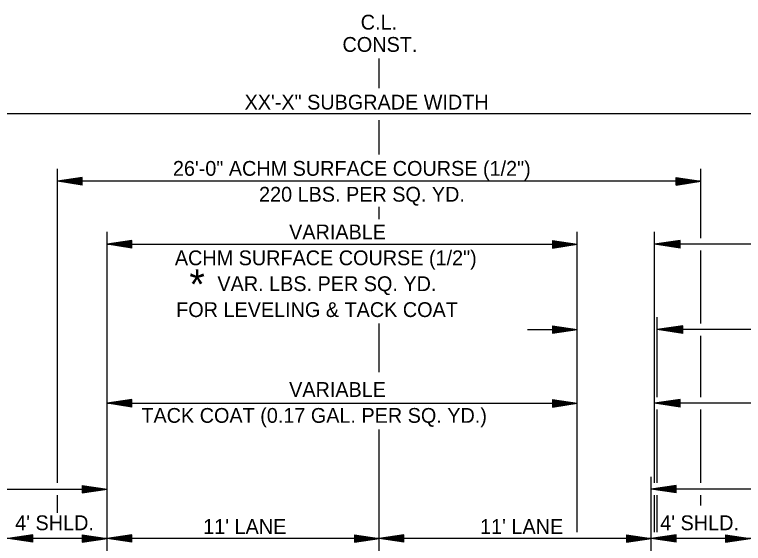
# Model space of a CAD drawing. Extents: x 138 to 3619, y -519 to 1449.
# Drawn here: x 460.6 to 755.2, y -282.8 to -68.8 of the extents above; entities that cross this region are included whole.
import ezdxf

# ---------------------------------------------------------------- set-up
doc = ezdxf.new("R2010")
doc.units = 0
for name, color, linetype in [('R_Annotation', 7, 'Continuous'), ('R_Centerline', 7, 'Continuous'), ('R_Dimension', 7, 'Continuous')]:
    doc.layers.add(name, color=color, linetype=linetype)

msp = doc.modelspace()

# ---------------------------------------------------------------- linework, layer by layer
at = {"layer": 'R_Centerline'}
for p, q in [((608, -98.62), (608, -86.64)), ((608, -125.42), (608, -111.52)), ((608, -151.62), (608, -146.64)), ((608, -213.43), (608, -193.8)), ((608, -272.33), (608, -236.67)), ((608, -320.11), (608, -272.33))]:
    msp.add_line(p, q, dxfattribs=at)
at = {"layer": 'R_Dimension'}
for p, q in [((414.37, -108.81), (801.63, -108.81)), ((477.98, -258.28), (477.98, -131.27)), ((738.02, -159.26), (738.02, -131.27)), ((487.98, -134.77), (477.98, -136.27)), ((487.98, -135.02), (479.65, -136.27)), ((487.98, -135.27), (481.37, -136.27)), ((487.98, -137.77), (487.98, -134.77)), ((728.02, -134.77), (738.02, -136.27)), ((728.02, -137.77), (728.02, -134.77)), ((728.02, -135.02), (736.35, -136.27)), ((728.02, -135.27), (734.63, -136.27)), ((487.98, -137.77), (477.98, -136.27)), ((738.02, -136.27), (477.98, -136.27)), ((487.98, -137.52), (479.65, -136.27)), ((487.98, -137.26), (481.37, -136.27)), ((487.98, -135.52), (483.04, -136.27)), ((487.98, -137.01), (483.04, -136.27)), ((487.98, -135.78), (484.73, -136.27)), ((487.98, -136.75), (484.73, -136.27)), ((487.98, -136.03), (486.4, -136.27)), ((487.98, -136.5), (486.4, -136.27)), ((728.02, -135.52), (732.96, -136.27)), ((728.02, -135.78), (731.27, -136.27)), ((728.02, -136.03), (729.6, -136.27)), ((728.02, -137.77), (738.02, -136.27)), ((728.02, -136.75), (731.27, -136.27)), ((728.02, -137.26), (734.63, -136.27)), ((728.02, -137.52), (736.35, -136.27)), ((728.02, -137.01), (732.96, -136.27)), ((728.02, -136.5), (729.6, -136.27)), ((498, -280.78), (498, -156.76)), ((688, -278.28), (688, -156.76)), ((719.27, -258.28), (719.27, -156.76)), ((508, -160.26), (498, -161.76)), ((508, -163.26), (498, -161.76)), ((498, -161.76), (688, -161.76)), ((508, -160.51), (499.67, -161.76)), ((508, -163.01), (499.67, -161.76)), ((508, -160.76), (501.39, -161.76)), ((508, -162.75), (501.39, -161.76)), ((508, -161.01), (503.06, -161.76)), ((508, -162.5), (503.06, -161.76)), ((508, -161.27), (504.75, -161.76)), ((508, -162.24), (504.75, -161.76)), ((508, -161.52), (506.42, -161.76)), ((508, -161.99), (506.42, -161.76)), ((508, -163.26), (508, -160.26)), ((678.02, -160.26), (688.02, -161.76)), ((678.02, -160.26), (678.02, -163.26)), ((678.02, -160.51), (686.35, -161.76)), ((678.02, -160.76), (684.63, -161.76)), ((678.02, -161.01), (682.96, -161.76)), ((678.02, -161.27), (681.27, -161.76)), ((678.02, -161.52), (679.6, -161.76)), ((678.02, -163.26), (688.02, -161.76)), ((678.02, -162.25), (681.27, -161.76)), ((678.02, -162.75), (684.63, -161.76)), ((678.02, -163.01), (686.35, -161.76)), ((678.02, -162.5), (682.96, -161.76)), ((678.02, -161.99), (679.6, -161.76)), ((729.65, -160.2), (719.27, -161.76)), ((969.27, -161.76), (719.27, -161.76)), ((729.65, -163.32), (719.27, -161.76)), ((729.65, -160.46), (721, -161.76)), ((729.65, -163.06), (721, -161.76)), ((729.65, -160.73), (722.79, -161.76)), ((729.65, -162.79), (722.79, -161.76)), ((729.65, -160.99), (724.51, -161.76)), ((729.65, -162.53), (724.51, -161.76)), ((729.65, -161.25), (726.27, -161.76)), ((729.65, -162.26), (726.27, -161.76)), ((729.65, -161.52), (728.01, -161.76)), ((729.65, -162), (728.01, -161.76)), ((729.65, -163.32), (729.65, -160.2)), ((738.02, -193.77), (738.02, -164.26)), ((720.32, -223.59), (720.32, -191.27)), ((668, -196.27), (688, -196.27)), ((678.02, -194.77), (688.02, -196.27)), ((678.02, -194.77), (678.02, -197.77)), ((678.02, -195.02), (686.35, -196.27)), ((678.02, -195.27), (684.63, -196.27)), ((678.02, -195.52), (682.96, -196.27)), ((678.02, -195.78), (681.27, -196.27)), ((678.02, -196.03), (679.6, -196.27)), ((678.02, -197.77), (688.02, -196.27)), ((678.02, -196.76), (681.27, -196.27)), ((678.02, -197.26), (684.63, -196.27)), ((678.02, -197.52), (686.35, -196.27)), ((678.02, -197.01), (682.96, -196.27)), ((678.02, -196.5), (679.6, -196.27)), ((730.7, -194.71), (720.32, -196.27)), ((970.32, -196.27), (720.32, -196.27)), ((730.7, -197.83), (720.32, -196.27)), ((730.7, -194.97), (722.05, -196.27)), ((730.7, -197.57), (722.05, -196.27)), ((730.7, -195.24), (723.83, -196.27)), ((730.7, -197.3), (723.83, -196.27)), ((730.7, -195.5), (725.56, -196.27)), ((730.7, -197.04), (725.56, -196.27)), ((730.7, -195.76), (727.32, -196.27)), ((730.7, -196.77), (727.32, -196.27)), ((730.7, -196.03), (729.06, -196.27)), ((730.7, -196.51), (729.06, -196.27)), ((730.7, -197.83), (730.7, -194.71)), ((738.02, -223.59), (738.02, -198.77)), ((508, -224.59), (498, -226.09)), ((498, -226.09), (688, -226.09)), ((508, -227.59), (498, -226.09)), ((508, -224.84), (499.67, -226.09)), ((508, -227.34), (499.67, -226.09)), ((508, -225.09), (501.39, -226.09)), ((508, -227.08), (501.39, -226.09)), ((508, -225.34), (503.06, -226.09)), ((508, -226.83), (503.06, -226.09)), ((508, -225.6), (504.75, -226.09)), ((508, -226.57), (504.75, -226.09)), ((508, -225.85), (506.42, -226.09)), ((508, -226.32), (506.42, -226.09)), ((508, -227.59), (508, -224.59)), ((678.02, -224.59), (688.02, -226.09)), ((678.02, -224.59), (678.02, -227.59)), ((678.02, -224.84), (686.35, -226.09)), ((678.02, -225.09), (684.63, -226.09)), ((678.02, -225.34), (682.96, -226.09)), ((678.02, -225.6), (681.27, -226.09)), ((678.02, -225.85), (679.6, -226.09)), ((678.02, -227.59), (688.02, -226.09)), ((678.02, -226.58), (681.27, -226.09)), ((678.02, -227.08), (684.63, -226.09)), ((678.02, -227.34), (686.35, -226.09)), ((678.02, -226.83), (682.96, -226.09)), ((678.02, -226.32), (679.6, -226.09)), ((729.65, -224.53), (719.27, -226.09)), ((969.27, -226.09), (719.27, -226.09)), ((729.65, -227.65), (719.27, -226.09)), ((729.65, -224.79), (721, -226.09)), ((729.65, -227.39), (721, -226.09)), ((729.65, -225.06), (722.79, -226.09)), ((729.65, -227.12), (722.79, -226.09)), ((729.65, -225.32), (724.51, -226.09)), ((729.65, -226.86), (724.51, -226.09)), ((729.65, -225.58), (726.27, -226.09)), ((729.65, -226.59), (726.27, -226.09)), ((729.65, -225.85), (728.01, -226.09)), ((729.65, -226.33), (728.01, -226.09)), ((729.65, -227.65), (729.65, -224.53)), ((720.32, -258.28), (720.32, -228.59)), ((738.02, -258.28), (738.02, -228.59)), ((718, -322.31), (718, -255.78)), ((258, -260.78), (498, -260.78)), ((488, -259.28), (498, -260.78)), ((488, -259.28), (488, -262.28)), ((488, -259.53), (496.33, -260.78)), ((488, -259.79), (494.61, -260.78)), ((488, -260.04), (492.95, -260.78)), ((488, -260.3), (491.25, -260.78)), ((488, -260.55), (489.58, -260.78)), ((488, -262.28), (498, -260.78)), ((488, -261.27), (491.25, -260.78)), ((488, -261.78), (494.61, -260.78)), ((488, -262.03), (496.33, -260.78)), ((488, -261.53), (492.95, -260.78)), ((488, -261.02), (489.58, -260.78)), ((728, -259.28), (718, -260.78)), ((958, -260.78), (718, -260.78)), ((728, -262.28), (718, -260.78)), ((728, -259.53), (719.67, -260.78)), ((728, -262.03), (719.67, -260.78)), ((728, -259.79), (721.39, -260.78)), ((728, -261.78), (721.39, -260.78)), ((728, -260.04), (723.06, -260.78)), ((728, -261.53), (723.06, -260.78)), ((728, -260.29), (724.75, -260.78)), ((728, -261.27), (724.75, -260.78)), ((728, -260.55), (726.42, -260.78)), ((728, -261.02), (726.42, -260.78)), ((728, -262.28), (728, -259.28)), ((477.98, -270.43), (477.98, -263.28)), ((719.27, -278.28), (719.27, -263.28)), ((720.32, -278.28), (720.32, -263.28)), ((738.02, -267.42), (738.02, -263.28)), ((468, -279.28), (458, -280.78)), ((468, -279.53), (459.67, -280.78)), ((468, -279.79), (461.39, -280.78)), ((468, -282.28), (468, -279.28)), ((488, -279.28), (498, -280.78)), ((488, -279.28), (488, -282.28)), ((488, -279.53), (496.33, -280.78)), ((488, -279.79), (494.61, -280.78)), ((508, -279.28), (498, -280.78)), ((508, -279.53), (499.67, -280.78)), ((508, -279.79), (501.39, -280.78)), ((508, -282.28), (508, -279.28)), ((598, -279.28), (608, -280.78)), ((598, -279.28), (598, -282.28)), ((598, -279.53), (606.33, -280.78)), ((598, -279.78), (604.61, -280.78)), ((618, -279.28), (608, -280.78)), ((618, -279.53), (609.67, -280.78)), ((618, -279.79), (611.39, -280.78)), ((618, -282.28), (618, -279.28)), ((708, -279.28), (718, -280.78)), ((708, -279.28), (708, -282.28)), ((708, -279.53), (716.33, -280.78)), ((708, -279.79), (714.61, -280.78)), ((728, -279.28), (718, -280.78)), ((728, -279.53), (719.67, -280.78)), ((728, -279.79), (721.39, -280.78)), ((728, -282.28), (728, -279.28)), ((748, -279.28), (758, -280.78)), ((748, -279.28), (748, -282.28)), ((748, -279.53), (756.33, -280.78)), ((748, -279.79), (754.61, -280.78)), ((801.63, -280.78), (414.37, -280.78)), ((468, -282.28), (458, -280.78)), ((468, -282.03), (459.67, -280.78)), ((468, -281.78), (461.39, -280.78)), ((468, -280.04), (463.06, -280.78)), ((468, -281.53), (463.06, -280.78)), ((468, -280.29), (464.75, -280.78)), ((468, -281.27), (464.75, -280.78)), ((468, -280.55), (466.42, -280.78)), ((468, -281.02), (466.42, -280.78)), ((488, -280.04), (492.95, -280.78)), ((488, -280.3), (491.25, -280.78)), ((488, -280.55), (489.58, -280.78)), ((488, -282.28), (498, -280.78)), ((488, -281.27), (491.25, -280.78)), ((488, -281.78), (494.61, -280.78)), ((488, -282.03), (496.33, -280.78)), ((488, -281.53), (492.95, -280.78)), ((488, -281.02), (489.58, -280.78)), ((498, -317.91), (498, -280.78)), ((508, -282.28), (498, -280.78)), ((508, -282.03), (499.67, -280.78)), ((508, -281.78), (501.39, -280.78)), ((508, -280.04), (503.06, -280.78)), ((508, -281.53), (503.06, -280.78)), ((508, -280.29), (504.75, -280.78)), ((508, -281.27), (504.75, -280.78)), ((508, -280.55), (506.42, -280.78)), ((508, -281.02), (506.42, -280.78)), ((598, -280.03), (602.94, -280.78)), ((598, -280.29), (601.25, -280.78)), ((598, -280.54), (599.58, -280.78)), ((598, -282.28), (608, -280.78)), ((598, -281.27), (601.25, -280.78)), ((598, -281.77), (604.61, -280.78)), ((598, -282.03), (606.33, -280.78)), ((598, -281.52), (602.94, -280.78)), ((598, -281.01), (599.58, -280.78)), ((618, -282.28), (608, -280.78)), ((618, -282.03), (609.67, -280.78)), ((618, -281.78), (611.39, -280.78)), ((618, -280.04), (613.06, -280.78)), ((618, -281.53), (613.06, -280.78)), ((618, -280.29), (614.75, -280.78)), ((618, -281.27), (614.75, -280.78)), ((618, -280.55), (616.42, -280.78)), ((618, -281.02), (616.42, -280.78)), ((708, -280.04), (712.95, -280.78)), ((708, -280.3), (711.25, -280.78)), ((708, -280.55), (709.58, -280.78)), ((708, -282.28), (718, -280.78)), ((708, -281.27), (711.25, -280.78)), ((708, -281.78), (714.61, -280.78)), ((708, -282.03), (716.33, -280.78)), ((708, -281.53), (712.95, -280.78)), ((708, -281.02), (709.58, -280.78)), ((728, -282.28), (718, -280.78)), ((728, -282.03), (719.67, -280.78)), ((728, -281.78), (721.39, -280.78)), ((728, -280.04), (723.06, -280.78)), ((728, -281.53), (723.06, -280.78)), ((728, -280.29), (724.75, -280.78)), ((728, -281.27), (724.75, -280.78)), ((728, -280.55), (726.42, -280.78)), ((728, -281.02), (726.42, -280.78)), ((748, -280.04), (752.95, -280.78)), ((748, -280.3), (751.25, -280.78)), ((748, -280.55), (749.58, -280.78)), ((748, -282.28), (758, -280.78)), ((748, -281.27), (751.25, -280.78)), ((748, -281.78), (754.61, -280.78)), ((748, -282.03), (756.33, -280.78)), ((748, -281.53), (752.95, -280.78)), ((748, -281.02), (749.58, -280.78))]:
    msp.add_line(p, q, dxfattribs=at)

# ---------------------------------------------------------------- texts
at = {"layer": 'R_Annotation'}
for s, height, p in [('C.L.', 6, (600.54, -74.89)), ('CONST.', 6, (593.17, -83.89)), ('XX\'-X" SUBGRADE WIDTH', 5.985, (553.61, -107.22)), ('26\'-0" ACHM SURFACE COURSE (1/2")', 5.985, (524.63, -134.03)), ('220 LBS. PER SQ. YD.', 5.985, (559.46, -144.5)), ('VARIABLE', 5.985, (571.61, -159.74)), ('ACHM SURFACE COURSE (1/2")', 5.985, (525.42, -170.22)), ('*', 12, (531.28, -183.89)), ('VAR. LBS. PER SQ. YD. ', 5.985, (542.62, -180.69)), ('FOR LEVELING & TACK COAT', 5.985, (525.96, -191.17)), ('VARIABLE', 5.985, (571.61, -223.5)), ('TACK COAT (0.17 GAL. PER SQ. YD.)', 5.985, (511.9, -233.98)), ("4' SHLD.", 6, (460.86, -277.43)), ("11' LANE", 6, (536.85, -278.94)), ("11' LANE", 6, (648.77, -278.94)), ("4' SHLD.", 6, (721.59, -277.43))]:
    msp.add_text(s, height=height, dxfattribs=at).set_placement(p)

doc.saveas('drawing.dxf')
